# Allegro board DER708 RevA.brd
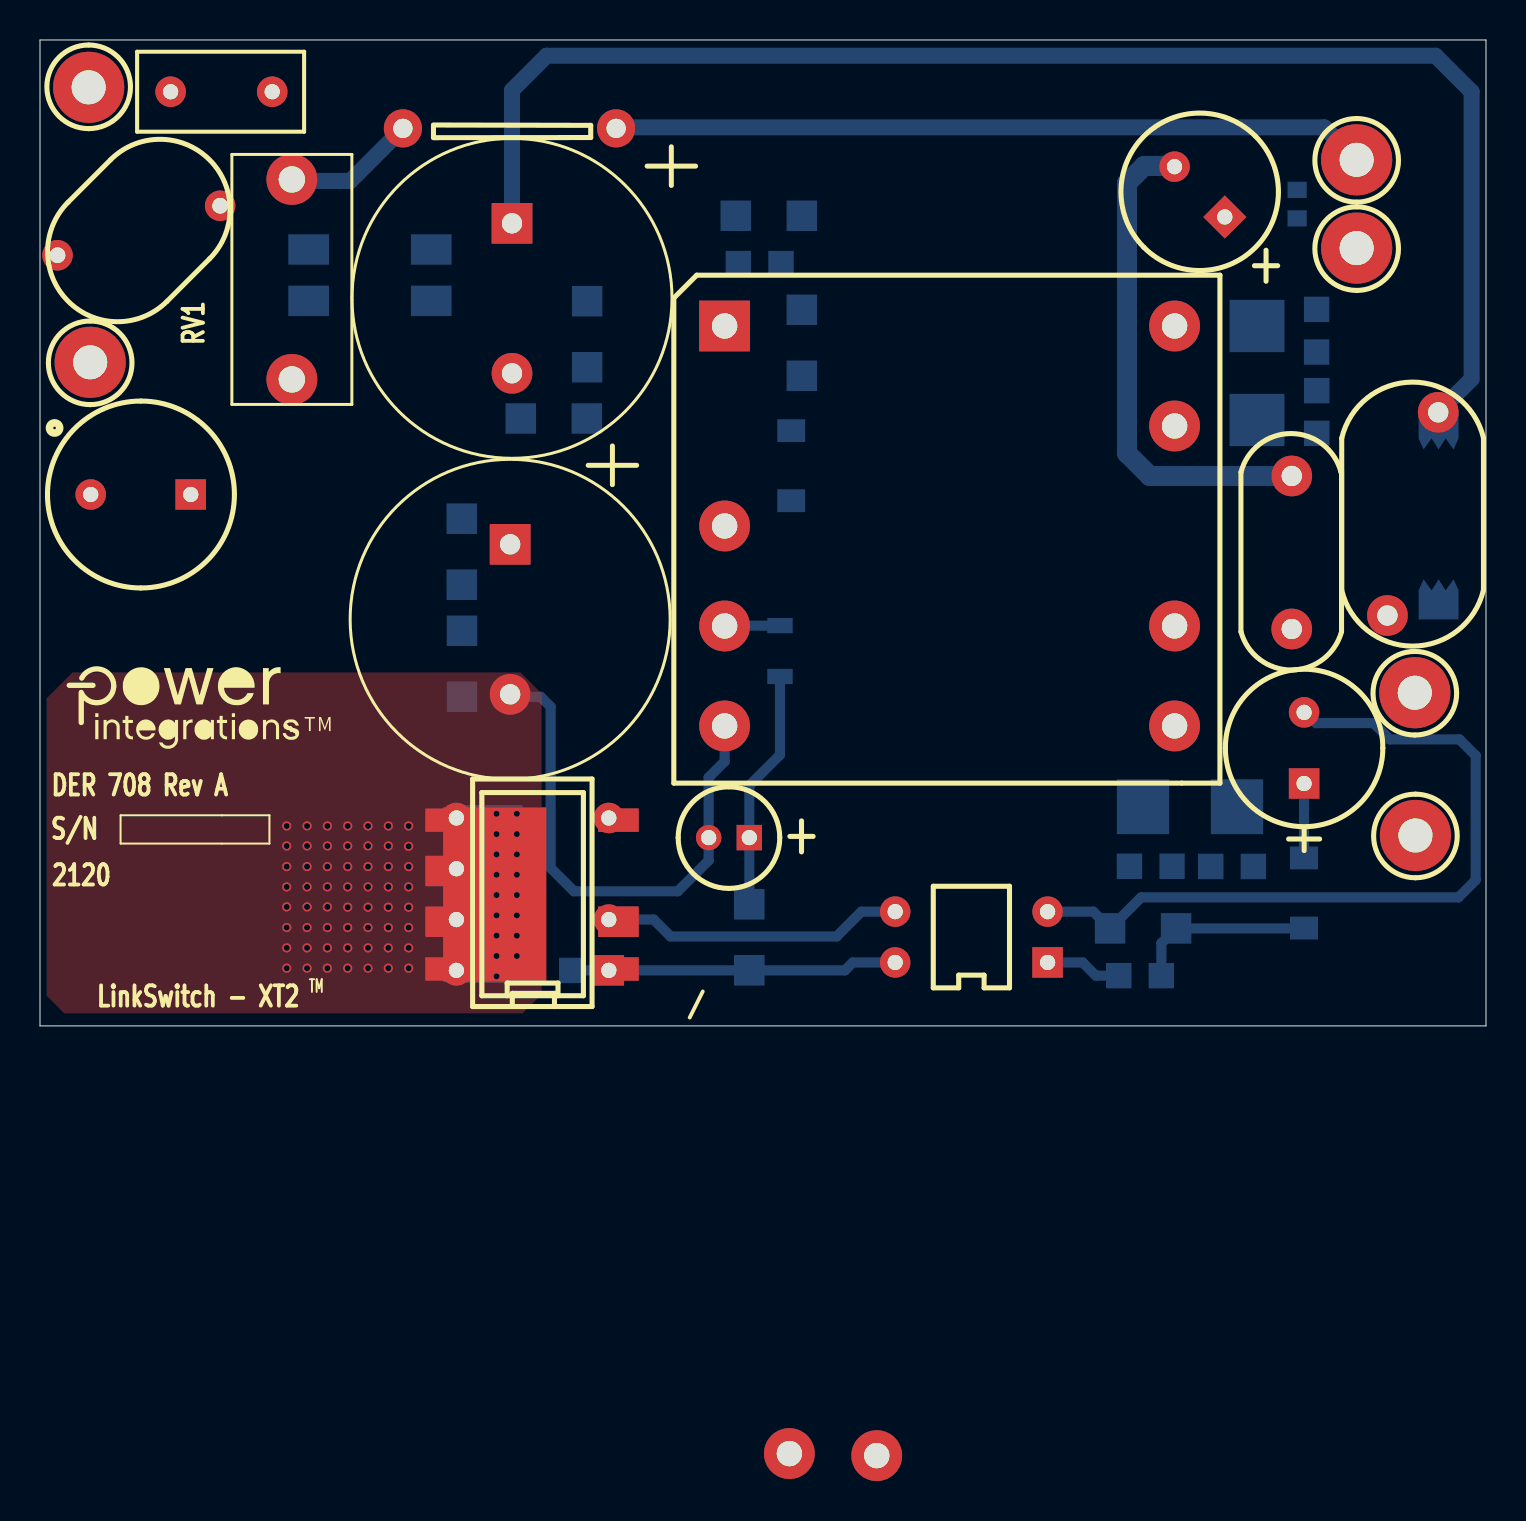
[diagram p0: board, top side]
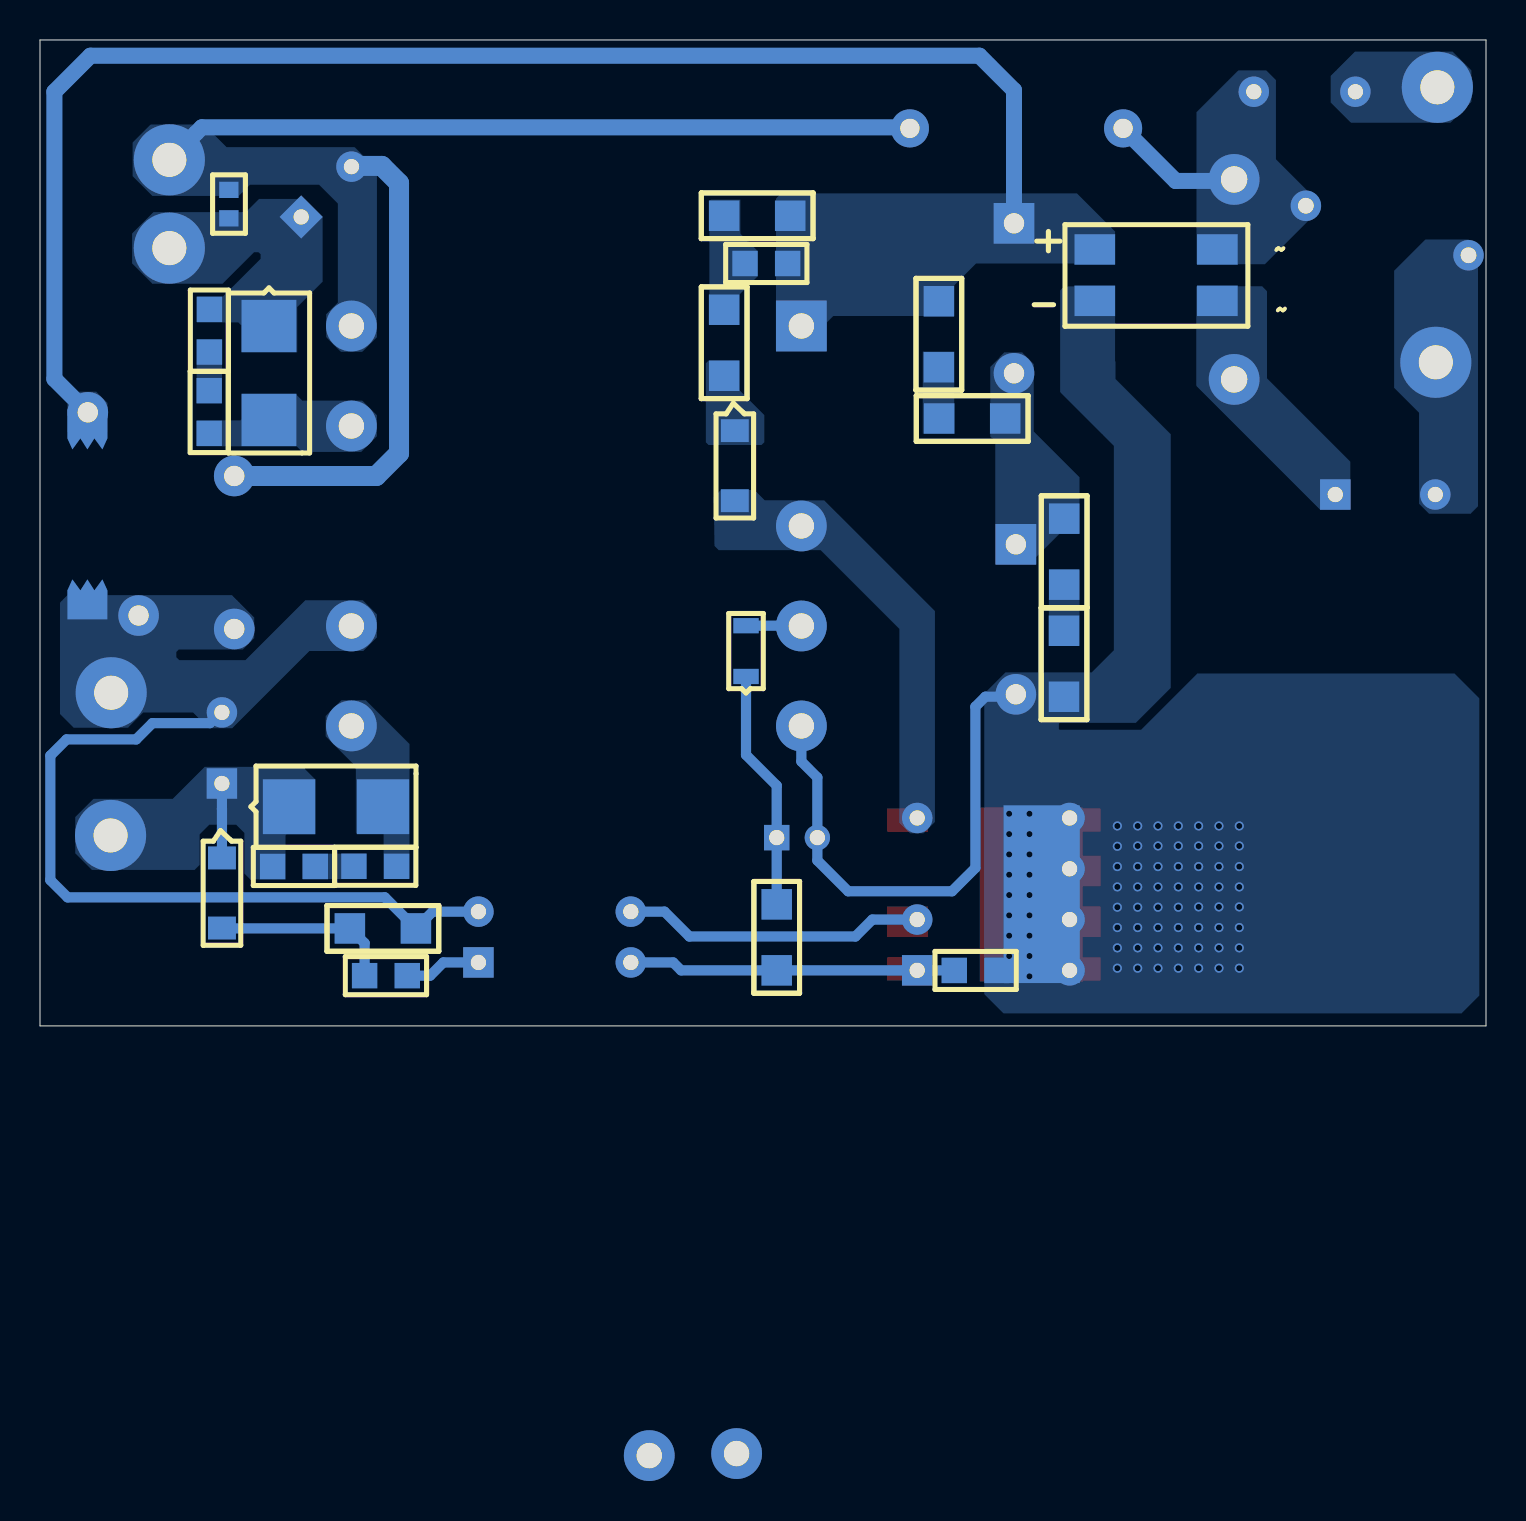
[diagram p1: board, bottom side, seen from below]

Outline 72.3 x 49.3 mm; copper layers: TOP, BOTTOM. Coordinates in mm from the lower left corner of the outline.
Outline path: 0,49.3 72.3,49.3 72.3,0 0,0 0,49.3

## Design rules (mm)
constraint set DEFAULT: min track width 0.508
net group SOURCE: nets N4275055

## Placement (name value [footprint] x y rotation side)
BR1  B10S-G  [PISMSOIC4]  13.43 36.26 90 bottom
C1  100 nF  [PI_NP_CAP12P5L6P0W10P0LSD040]  12.59 42.33 270 top
C2  82 uF  [PIPOLCAPD16X25MMD40]  23.6 40.13 270 top
C3  82 uF  [PIPOLCAPD16X25MMD40]  23.51 24.08 270 top
C4  1000 pF  [PISMC0805]  37.05 38.12 180 bottom
C5  100 nF  [PISMC0805]  26.59 2.77 180 bottom
C6  2.2 nF  [PINPYCAPRAD540X290LS400040]  69.91 30.68 270 top
C7  22 uF  [PIPOLCAPCLYD200LS80030]  35.46 9.41 180 top
C8  1 nF  [PISMC0805]  63.84 29.63 90 bottom
C9  1 nF  [PISMC0805]  54.47 7.98 0 bottom
C10  330 uF  [PIPOLCAPCLYD320LS140030]  59.24 40.45 135 top
C11  330 uF  [PIPOLCAPCLYD320LS140030]  63.2 12.12 90 top
C12  330 pF  [PINPYCAPRAD470X210LS380040]  62.59 28.5 270 top
D1  SM4007PL-TP  [PI_SM_SOD-123_12]  37.56 29.77 270 bottom
D2  BAV19WS  [PISMSOD323]  37 17.47 90 bottom
D3  ES2B-E3/52T  [PISMDO214AA12]  59.85 10.96 180 bottom
D4  ES2B-E3/52T  [PISMDO214AA12]  60.85 35 270 bottom
F1  6.3 A  [PI_V_AX_BEL_0697H]  6.53 46.71 0 top
JP1  J  [PI_JUMPER400]  13.15 44.65 0 top
L  BLK  [PITPKEYSTONE125X125]  2.43 46.93 180 top
L1  1.5 mH  [PI_CHOKE_RLB9012_D2]  7.54 26.57 180 top
N  WHT  [PITPKEYSTONE125X125]  2.51 33.18 0 top
NOREF  -  []  -233.6 -145.28 0 top
NOREF#2  -  []  -155.78 53.73 0 top
NOREF#3  -  []  0 0 0 top
NOREF#4  -  []  1.35 18.41 0 top
NOREF#5  -  []  0 0 90 top
R1  5.1 M  [PISMR1206]  27.36 36.24 270 bottom
R2  5.1 M  [PISMR1206]  27.34 30.37 180 bottom
R3  5.1 M  [PISMR1206]  21.09 25.36 270 bottom
R4  5.1 M  [PISMR1206]  21.1 19.76 270 bottom
R5  200 k  [PISMR1206]  38.09 40.51 180 bottom
R6  47  [PISMR1206]  38.09 35.81 270 bottom
R7  3 k  [PISMR1206]  35.46 2.78 90 bottom
R9  16  [PISMR0805]  63.83 33.7 90 bottom
R10  16  [PISMR0805]  58.54 7.97 0 bottom
R11  100  [PISMR0805]  56.07 2.51 180 bottom
R12  562  [PISMR1206]  56.81 4.87 180 bottom
R13  6.2 k  [PISMR0603]  62.86 40.38 90 bottom
RTN1  BLK  [PITPKEYSTONE125X125]  68.74 16.66 0 top
RTN2  BLU  [PITPKEYSTONE125X125]  65.83 43.31 0 top
RV1  350 VAC  [PI_RADD10P5XT8P1XLS7P5D031]  6.18 43.84 225 top
SG1  6.5mm gap  [PI_SPARK_GAP_6P5MM]  69.93 25.58 270 bottom
T1  EFD25  [PI_BOBBIN_EFD25_10P]  34.23 35 0 top
U1  LNK3696P  [PIICDIP8CSHORT5678]  28.44 2.78 90 top
U2  LNK3696G  [PIICSMD8CSHORT5678]  28.92 2.85 90 top
U3  LTV817A  [PI_DIP4]  50.38 3.17 90 top
VOUT1  RED  [PITPKEYSTONE125X125]  68.77 9.52 0 top
VOUT2  YEL  [PITPKEYSTONE125X125]  65.83 38.89 0 top
VR1  MMSZ5247BT1G  [PI_SM_SOD-123_12]  63.2 8.4 270 bottom

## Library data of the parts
BR1 = DIODE BRIDGE_~~+-: alternate symbols: (pi_sm_soic4_slot)
C1 C4 C5 C12 = CAP NP
C2 C3 = CAP POL: alternate symbols: (pipolcapd16x25mmd40H)
C6 = CAP NP: alternate symbols: (pinpycaprad540x290ls400040h)
C7 = CAP POL: alternate symbols: (pipolcapclyd200ls80030h)
C8 C9 = CAP NP: alternate symbols: (pismc0805_1)
C10 C11 = CAP POL
D1-D4 = DIODE
F1 = FUSE: alternate symbols: (PI_V_AX_BEL_0697H_H)
JP1 = JUMPER_1
L N RTN1 RTN2 VOUT1 VOUT2 = TESTPOINT
L1 = INDUCTOR_DOT2
R1-R7 R9-R13 = R
RV1 = VARISTOR: alternate symbols: (pi_radD10p5xT8p1xLS7p5d031H)
SG1 = SPARK_GAP
T1 = BEFD25_1
U1 = LNK3696_3
U2 = LNK3696_4: alternate symbols: (piicsmd8cshort5678)
U3 = OPTO_A_B
VR1 = DIODE_ZENER

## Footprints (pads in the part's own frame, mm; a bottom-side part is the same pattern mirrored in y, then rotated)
PI_BOBBIN_EFD25_10P
  rect 2.54x2.54 hole 1.27: 1(0,0)
  round 2.54 hole 1.27: 2(3.238,-56.386) 3(0,-10) 4(0,-15.001) 5(0,-20) 6(22.499,-20) 7(22.499,-15.001) 8(7.606,-56.487) 9(22.499,-5.001) 10(22.499,0)
PI_CHOKE_RLB9012_D2
  rect 1.524x1.524 hole 0.762: 1(0,0)
  round 1.524 hole 0.762: 2(5.001,0)
PI_DIP4
  rect 1.524x1.524 hole 0.762: 1(0,0)
  round 1.524 hole 0.762: 2(2.54,0) 3(2.54,7.62) 4(0,7.62)
PI_JUMPER400
  round 1.905 hole 0.965: 1(5,0.23) 2(15.66,0.23)
PI_NP_CAP12P5L6P0W10P0LSD040
  round 2.54 hole 1.321: 1(0,0) 2(10,0)
PI_RADD10P5XT8P1XLS7P5D031
  round 1.524 hole 0.787: 1(0,4) 2(7.5,0)
PI_SM_SOD-123_12
  rect 1.143x1.397 smd: 1(0,0) 2(3.505,0)
PI_SPARK_GAP_6P5MM
  custom 0.5x0.5 smd: 1(-4.25,0) 2(4.25,0)
PI_V_AX_BEL_0697H
  round 1.524 hole 0.762: 1(0,0) 2(5.08,0)
PIICDIP8CSHORT5678
  rect 1.524x1.524 hole 0.762: 1(0,0)
  round 1.524 hole 0.762: 2(2.54,0) 4(7.62,0) 5(7.62,7.62) 6(5.08,7.62) 7(2.54,7.62) 8(0,7.62)
PIICSMD8CSHORT5678
  rect 1.168x2.032 smd: 1(0,0) 4(7.442,0) 5(7.442,8.636) 8(0,8.636)
  rect 1.524x2.032 smd: 2(2.362,0) 6(4.902,8.636) 7(2.362,8.636)
PINPYCAPRAD470X210LS380040
  round 2.032 hole 1.016: 1(1,0) 2(8.652,0)
PINPYCAPRAD540X290LS400040
  round 2.032 hole 1.016: 1(0,0) 2(10.16,-2.54)
PIPOLCAPCLYD200LS80030
  rect 1.27x1.27 hole 0.762: 1(0,0)
  round 1.27 hole 0.762: 2(2.032,0)
PIPOLCAPCLYD320LS140030
  rect 1.524x1.524 hole 0.762: 1(0,0)
  round 1.524 hole 0.762: 2(3.556,0)
PIPOLCAPD16X25MMD40
  rect 2.032x2.032 hole 1.016: 1(0,0)
  round 2.032 hole 1.016: 2(7.5,0)
PISMC0805
  rect 1.27x1.27 smd: 1(0,0) 2(2.134,0)
PISMDO214AA12
  rect 2.616x2.743 smd: 1(0,0) 2(4.699,0)
PISMR0603
  rect 0.813x0.965 smd: 1(0,0) 2(1.422,0)
PISMR0805
  rect 1.27x1.27 smd: 1(0,0) 2(2.134,0)
PISMR1206
  rect 1.524x1.524 smd: 1(0,0) 2(3.302,0)
PISMSOD323
  rect 0.762x1.27 smd: 1(0,0) 2(2.54,0)
PISMSOIC4
  rect 1.524x2.032 smd: 1(0,0) 2(2.571,0) 3(2.571,6.129) 4(0,6.129)
PITPKEYSTONE125X125
  round 3.556 hole 1.702: 1(0,0)

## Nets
LINE1: BR1.2 C1.1 F1.2 JP1.1 RV1.1
LINE2: C10.2 C12.1 JP1.2 R13.2 RTN2.1 T1.10
SOURCE: BR1.4 C3.2 C5.2 C7.2 R4.2 T1.5 U1.5 U1.6 U1.7 U1.8(S8) U2.5 U2.6 U2.7 U2.8(S8)
N4274193: BR1.3 C2.1 C4.2 C6.1 R1.1 R5.2 SG1.1 T1.1
N4274205: C6.2 C11.2 C12.2 R12.2 RTN1.1 SG1.2 T1.7 U3.2
N4274243: C8.1 D4.2 T1.9
N4274251: C8.2 R9.1
N4274255: C10.1 D4.1 R9.2 R13.1 VOUT2.1
N4274603: D1.2 T1.3 U1.4 U2.4
N4274611: C9.1 D3.2 T1.6
N4274619: C11.1 D3.1 R10.2 VOUT1.1 VR1.1
N4274661: C4.1 R5.1 R6.1
N4274675: R1.2 R2.1
N4274777: D2.2 T1.4
N4274879: F1.1 L.1
N4274899: C2.2 C3.1 R2.2 R3.1
N4274903: D1.1 R6.2
N4275055: C7.1 D2.1 R7.2
N4275119: R11.1 R12.1 VR1.2
N4275169: R3.2 R4.1
N4275211: U1.2 U2.2 U3.3(E)
N4275423: R11.2 U3.1
N4275517: C5.1 R7.1 U1.1 U2.1 U3.4
N4276562: C9.2 R10.1
N4280018: BR1.1 C1.2 L1.1
N4280035: L1.2 N.1 RV1.2

Pads without a net: T1 2 8

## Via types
v1: diameter 0.457, hole 0.305, TOP to BOTTOM, 73 vias

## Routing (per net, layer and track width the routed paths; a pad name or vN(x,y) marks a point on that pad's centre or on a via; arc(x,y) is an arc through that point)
LINE1: length 6.3
  BOTTOM w0.8: JP1.1 15.52,42.25 12.92,42.25
LINE2: length 62.7
  BOTTOM w0.508: JP1.2 28.81,44.93
  BOTTOM w0.8: 28.81,44.93 64.21,44.93 64.49,44.65 RTN2.1
  BOTTOM w1: C12.1 55.49,27.5 54.35,28.64 54.35,42.14 55.21,43 56.69,43 C10.2
SOURCE: length 26.4
  BOTTOM w0.508: T1.5 34.23,13.22 33.43,12.42 C7.2 33.43,8.27 31.89,6.73 26.7,6.73 25.53,7.9 25.53,15.96 25.03,16.46 23.51,16.46
  vias: v1(12.34,10) v1(12.34,9) v1(12.34,7.97) v1(12.34,6.95) v1(12.34,5.95) v1(12.34,4.92) v1(12.34,3.9) v1(12.34,2.89) v1(13.35,10) v1(13.35,9) v1(13.35,7.97) v1(13.35,6.95) v1(13.35,5.95) v1(13.35,4.92) v1(13.35,3.9) v1(13.35,2.89) v1(14.37,10) v1(14.37,9) v1(14.37,7.97) v1(14.37,6.95) v1(14.37,5.95) v1(14.37,4.92) v1(14.37,3.9) v1(14.37,2.89) v1(15.38,10) v1(15.38,9) v1(15.38,7.97) v1(15.38,6.95) v1(15.38,5.93) v1(15.38,4.92) v1(15.38,3.9) v1(15.38,2.89) v1(16.4,10) v1(16.4,9) v1(16.4,7.97) v1(16.4,6.95) v1(16.4,5.93) v1(16.4,4.92) v1(16.4,3.9) v1(16.4,2.89) v1(17.42,10) v1(17.42,9) v1(17.42,7.97) v1(17.42,6.95) v1(17.42,5.93) v1(17.42,4.92) v1(17.42,3.9) v1(17.42,2.89) v1(18.43,10) v1(18.43,8.98) v1(18.43,7.97) v1(18.43,6.95) v1(18.43,5.93) v1(18.43,4.92) v1(18.43,3.9) v1(18.43,2.89) v1(22.83,10.61) v1(22.83,9.59) v1(22.83,8.57) v1(22.83,7.56) v1(22.83,6.54) v1(22.83,5.53) v1(22.83,4.51) v1(22.83,3.49) v1(22.83,2.48) v1(23.84,10.61) v1(23.84,9.59) v1(23.84,8.57) v1(23.84,7.56) v1(23.84,6.54) v1(23.84,5.53) v1(23.84,4.51) v1(23.84,3.49)
N4274193: length 72.8
  BOTTOM w0.8: C2.1 23.6,46.79 25.33,48.51 69.78,48.51 71.58,46.71 71.58,32.35 C6.1
N4274205: length 38.5
  BOTTOM w0.508: U3.2 52.67,5.71 R12.2 55.06,6.43 70.92,6.43 71.78,7.29 71.78,13.51 70.97,14.33 67.49,14.33 66.68,15.14 63.81,15.14 63.27,15.68 C11.2
N4274619: length 3.7
  BOTTOM w0.508: C11.1 63.2,10.85 63.2,10.85 VR1.1
N4274777: length 2.8
  BOTTOM w0.508: D2.2 34.25,20.01 T1.4
N4275055: length 12
  BOTTOM w0.508: D2.1 37,13.55 35.46,12.02 C7.1 R7.2
N4275119: length 9.1
  BOTTOM w0.508: VR1.2 63.18,4.87 62.66,4.87 62.65,4.87 R12.1 56.07,4.14 R11.1
N4275211: length 15.2
  BOTTOM w0.508: U1.2 30.68,5.32 31.53,4.47 39.83,4.47 41.07,5.71 U3.3
N4275423: length 3.8
  BOTTOM w0.508: U3.1 52.13,3.17 52.79,2.51 R11.2
N4275517: length 16.3
  BOTTOM w0.508: U3.4 40.64,3.17 40.25,2.78 R7.1 U1.1 26.59,2.78 C5.1

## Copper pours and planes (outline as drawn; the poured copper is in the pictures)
LINE1 on BOTTOM: 8.55,41.39 8.55,40.59 11.05,38.09 14.48,38.09 14.48,45.69 12.38,47.78 10.99,47.78 10.5,47.3 10.5,43.33
LINE2 on BOTTOM: 55.45,34.44 56.19,33.71 57.26,33.71 57.99,34.44 57.99,35.59 57.41,36.17 57.41,41.12 58.35,42.06 61.8,42.06 62.36,41.5 66.68,41.5 67.67,42.49 67.67,44.17 66.77,45.07 64.1,45.07 62.97,43.94 56.57,43.94 55.45,42.82
SOURCE on TOP (solid shape): 25.32,2.21 20.16,2.21 20.16,10.92 25.32,10.92
SOURCE on BOTTOM (solid shape): 24.12,2.14 20.31,2.14 20.31,11.03 24.12,11.03
SOURCE on TOP: 0.33,16.38 0.33,1.51 1.22,0.62 24.12,0.62 25.09,1.59 25.09,16.61 24.02,17.68 1.63,17.68
SOURCE on BOTTOM: 15.76,16.9 17.51,15.15 21.32,15.15 21.36,15.11 21.36,14.85 21.32,14.81 17.25,14.81 14.57,17.49 14.43,17.62 1.58,17.62 0.33,16.38 0.33,1.51 1.22,0.62 24.12,0.62 25.09,1.59 25.09,16.61 24.02,17.68 19.71,17.68 18.61,18.79 18.61,29.01 21.29,31.69 21.29,36.78 21.09,36.98 18.55,36.98 18.55,33.24 18.52,33.22 18.52,32.34 15.76,29.58
N4274193 on BOTTOM: 33.01,33.75 35.48,33.75 35.5,33.77 35.5,41.37 35.24,41.63 20.45,41.63 18.55,39.72 18.55,38.13 25.5,38.13 26.59,37.03 26.59,35.48 26.6,35.5 32.63,35.5 32.96,35.17 32.96,33.8
N4274193 on BOTTOM: 68.92,29.66 70.71,29.66 70.9,29.66 70.93,29.69 70.93,31.12 70.33,31.71 69.49,31.71 68.92,31.15
N4274205 on BOTTOM: 58.83,18.75 62.69,14.88 63.86,14.88 64.65,15.67 67.14,15.67 67.9,14.91 70.62,14.91 71.3,15.6 71.3,21.16 70.93,21.54 62.7,21.54 61.59,20.42 61.59,19.39 62.16,18.82 65.36,18.82 65.49,18.69 65.49,18.44 65.33,18.29 62.03,18.29 59.03,21.29 56.39,21.29 56.16,21.28 55.45,20.57 55.45,19.43 56.14,18.75
N4274243 on BOTTOM: 56.19,31.27 55.45,30.53 55.45,29.49 56.24,28.7 59.19,28.7 59.47,28.98 64.44,28.98 64.44,30.25 64.42,30.28 62.28,30.28 62.21,30.35 62.21,31.57 62.18,31.6 59.52,31.6 59.19,31.27
N4274251 on BOTTOM: 63.2,34.34 63.2,31.14 64.47,31.14 64.47,34.34
N4274255 on BOTTOM: 67.69,39.62 66.63,40.69 62.01,40.69 61.34,41.35 59.06,41.35 58.17,40.46 58.17,37.21 59.44,35.94 59.44,33.68 62.23,33.68 62.23,35.03 62.39,35.18 64.44,35.18 64.44,36.47 63.15,36.47 61.27,38.35 61.27,38.58 61.37,38.68 61.6,38.68 63.17,37.11 66.68,37.11 67.69,38.13
N4274603 on BOTTOM: 38.36,23.79 38.58,24 38.61,26.45 38.26,26.8 36.58,26.8 36.07,26.29 33.72,26.28 33.09,26.28 27.55,20.74 27.55,10.2 28.12,9.63 28.8,9.63 29.33,10.16 29.33,19.85 33.27,23.79
N4274611 on BOTTOM: 53.83,14.1 53.83,7.34 55.12,7.34 55.12,9.6 56.44,9.6 56.51,9.66 56.51,12.97 58.02,14.48 58.02,15.49 57.23,16.28 56.01,16.28
N4274619 on BOTTOM: 58.53,12.32 58.53,9.58 59.97,9.58 60.02,9.53 60.02,7.32 61.32,7.32 61.33,7.33 61.79,7.33 62.08,7.62 62.08,9.65 62.49,10.06 63.83,10.06 64.32,9.58 64.32,8.05 64.57,7.8 69.7,7.8 70.54,8.64 70.54,10.44 69.63,11.35 65.66,11.35 64.06,12.95 59.16,12.95
N4274661 on BOTTOM: 37.28,41.32 37.28,39.61 36.42,38.75 36.42,37.48 37.33,36.57 37.33,35.07 38.83,35.07 38.83,41.24 38.75,41.32
N4274675 on BOTTOM: 26.59,33.72 26.59,29.61 28.16,29.61 28.16,33.72
N4274879 on BOTTOM: 0.73,47.78 0.73,46.2 1.77,45.16 6.75,45.16 7.77,46.18 7.77,47.5 6.55,48.72 1.67,48.72
N4274899 on BOTTOM: 24.32,33.41 24.79,32.95 24.79,29.47 24.54,29.22 24.54,23.09 24.51,23.06 22.87,23.06 22.75,23.18 21.32,24.61 20.45,24.61 20.45,24.61 20.33,24.61 20.32,24.61 20.32,27.43 20.34,27.45 22.61,29.72 22.61,33.1 23.19,33.68 24.08,33.68 24.32,33.44
N4274903 on BOTTOM: 37.33,31.79 36.09,30.55 36.09,29.19 36.22,29.05 38.87,29.05 39.01,29.18 39.01,33.14 38.88,33.26 37.33,33.26
N4275169 on BOTTOM: 21.84,21.41 21.84,22.75 20.31,22.75 20.32,22.74 20.32,19.02 20.35,19 21.84,19 21.86,19.02 21.86,21.39
N4276562 on BOTTOM: 55.99,8.61 55.99,7.34 59.16,7.34 59.19,7.37 59.19,8.61
N4280018 on BOTTOM: 6.79,25.81 8.29,25.81 14.48,32 14.48,36.97 14.47,36.98 11.19,36.98 10.95,36.74 10.95,32.38 6.79,28.22
N4280035 on BOTTOM: 0.4,25.98 0.78,25.61 2.84,25.61 3.35,26.11 3.35,30.66 4.59,31.9 4.59,37.77 3.04,39.32 0.86,39.32 0.4,38.86

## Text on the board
Ref Des/Silkscreen Top: TM | S/N | DER 708 Rev A | 2120 | LinkSwitch - XT2 | /
User.5: SLOT
User.6: NOTES: PLEASE DELETE: | 14.  FAB HOUSE LOGO,DATE CODE TO BE IN SILK SCREEN ONLY.DO NOT USE COPPER. | 13.  MATERIAL FR4 COPPER 2oz THICKNESS 0.062"
User.8: FIGURE | FINISHED_SIZE | 12.0 | 30.0 | 31.0 | 38.0 | 40.0 | 50.0 | 52.0 | 67.0 | DRILL CHART: TOP to BOTTOM | ALL UNITS ARE IN MILS | TOLERANCE_DRILL | +3.0/-3.0 | PLATED | QTY | 73 | 21 | 2 | 8 | 10 | 6 | 124 | TOTAL HOLES:
